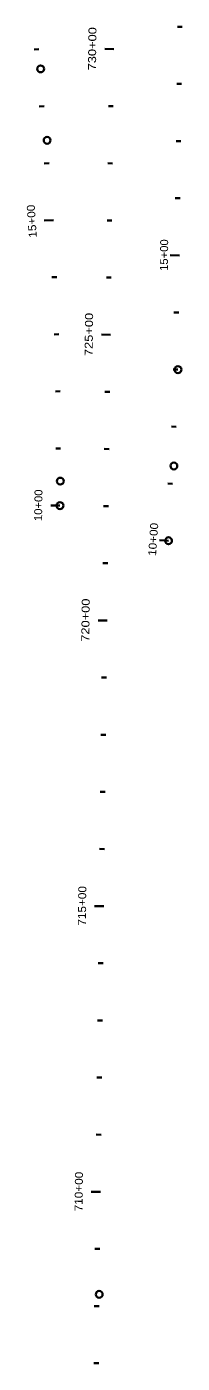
# Model space of a CAD drawing. Extents: x 2357892 to 2370172, y 6966790 to 6985499.
# Drawn here: x 2364291 to 2364564, y 6971527 to 6973865 of the extents above; entities that cross this region are included whole.
import ezdxf
from ezdxf.enums import TextEntityAlignment as Align

# ---------------------------------------------------------------- set-up
doc = ezdxf.new("R2010")
doc.units = 0
doc.header["$LTSCALE"] = 5.6
doc.layers.add('28', color=7, linetype='Continuous', lineweight=35)

msp = doc.modelspace()

# ---------------------------------------------------------------- linework, layer by layer
at = {"layer": '28'}
for p, q in [((2364563.619, 6973865.363), (2364555.119, 6973865.471)), ((2364312.269, 6973826.1), (2364303.793, 6973825.456)), ((2364443.609, 6973826.386), (2364427.61, 6973826.574)), ((2364562.339, 6973765.371), (2364553.84, 6973765.48)), ((2364321.087, 6973726.49), (2364312.623, 6973725.719)), ((2364442.429, 6973726.393), (2364433.93, 6973726.493)), ((2364561.059, 6973665.379), (2364552.56, 6973665.488)), ((2364330.025, 6973626.89), (2364321.555, 6973626.177)), ((2364441.249, 6973626.4), (2364432.749, 6973626.5)), ((2364559.78, 6973565.387), (2364551.28, 6973565.496)), ((2364337.535, 6973527.172), (2364321.57, 6973526.11)), ((2364440.068, 6973526.406), (2364431.569, 6973526.507)), ((2364558.5, 6973465.395), (2364542.501, 6973465.6)), ((2364343.304, 6973427.339), (2364334.814, 6973426.922)), ((2364438.888, 6973426.413), (2364430.389, 6973426.514)), ((2364557.22, 6973365.404), (2364548.721, 6973365.512)), ((2364347.329, 6973327.42), (2364338.834, 6973327.152)), ((2364437.708, 6973326.42), (2364421.709, 6973326.609)), ((2364555.941, 6973265.412), (2364547.442, 6973265.521)), ((2364349.61, 6973227.446), (2364341.111, 6973227.326)), ((2364436.527, 6973226.427), (2364428.028, 6973226.528)), ((2364552.916, 6973165.463), (2364544.426, 6973165.868)), ((2364350.146, 6973127.447), (2364341.646, 6973127.476)), ((2364435.347, 6973126.434), (2364426.848, 6973126.535)), ((2364546.575, 6973065.667), (2364538.097, 6973066.276)), ((2364349.097, 6973027.453), (2364333.098, 6973027.667)), ((2364434.167, 6973026.441), (2364425.667, 6973026.542)), ((2364539.412, 6972965.924), (2364523.453, 6972967.07)), ((2364432.986, 6972926.448), (2364424.487, 6972926.549)), ((2364431.806, 6972826.455), (2364415.807, 6972826.644)), ((2364430.626, 6972726.462), (2364422.126, 6972726.563)), ((2364429.445, 6972626.469), (2364420.946, 6972626.57)), ((2364428.265, 6972526.476), (2364419.766, 6972526.576)), ((2364427.085, 6972426.483), (2364418.585, 6972426.583)), ((2364425.904, 6972326.49), (2364409.905, 6972326.679)), ((2364424.724, 6972226.497), (2364416.225, 6972226.597)), ((2364423.544, 6972126.504), (2364415.044, 6972126.604)), ((2364422.363, 6972026.511), (2364413.864, 6972026.611)), ((2364421.183, 6971926.518), (2364412.684, 6971926.618)), ((2364420.003, 6971826.525), (2364404.004, 6971826.714)), ((2364418.822, 6971726.532), (2364410.323, 6971726.632)), ((2364417.661, 6971626.539), (2364409.161, 6971626.624)), ((2364417.096, 6971526.541), (2364408.596, 6971526.551))]:
    msp.add_line(p, q, dxfattribs=at)
for centre in [(2364315.139, 6973791.755), (2364326.529, 6973666.788), (2364555.941, 6973265.423), (2364548.816, 6973096.87), (2364349.668, 6973070.261), (2364349.097, 6973027.453), (2364539.412, 6972965.924), (2364417.885, 6971647.084)]:
    msp.add_circle(centre, 6, dxfattribs=at)

# ---------------------------------------------------------------- texts
for s, rotation, width, p in [('730+00', 89.324, 1.2, (2364412.612, 6973826.834)), ('15+00', 93.807, 1.1, (2364306.573, 6973525.579)), ('15+00', 89.267, 1.05, (2364538.503, 6973465.741)), ('725+00', 89.324, 1.2, (2364406.711, 6973326.869)), ('10+00', 89.235, 1.05, (2364318.101, 6973027.961)), ('10+00', 85.892, 1.1, (2364519.499, 6972967.859)), ('720+00', 89.324, 1.2, (2364400.809, 6972826.904)), ('715+00', 89.324, 1.1, (2364394.908, 6972326.938)), ('710+00', 89.324, 1.1, (2364389.006, 6971826.973))]:
    msp.add_text(s, height=14, rotation=rotation, dxfattribs=dict(at, width=width)).set_placement(p, align=Align.CENTER)

doc.saveas('drawing.dxf')
